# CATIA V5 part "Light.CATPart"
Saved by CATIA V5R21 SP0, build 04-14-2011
Part number: Light
Bounding box of the stored display mesh (mm): x -34.99 to 34.99, y -34.99 to 35, z -65 to 0
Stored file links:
  G:\CATIA\Class\Class_3D\Light.CATPart
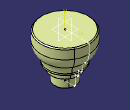
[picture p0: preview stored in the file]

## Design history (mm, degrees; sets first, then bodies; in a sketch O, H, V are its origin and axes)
Set1 "surface"
  Revol1: Element1 Sketch1, Angle1 360
Set2 "Operation"
  Sketch1 on yz-plane, origin (0, 0, 0), H (0, 1, 0), V (0, 0, 1)
    axis line L1 (0, 88.3428) -> (0, -107.8495)
    point P1 (0, 88.3428)
    line L2 (0, 0) -> (33.5858, 0)
    point P3 (35, 0)
    line L3 (35, -1.4142) -> (35, -14)
    point P4 (35, -14)
    arc A1 centre (15, -14) radius 20 from (35, -14) to (29.2857, -27.9971) cw
    arc A2 centre (40, -38.4949) radius 15 from (29.2857, -27.9971) to (25, -38.4949) ccw
    line L4 (25, -38.4949) -> (25, -40.5858)
    line L5 (23.5858, -42) -> (20, -42)
    line L6 (20, -42) -> (20, -48.5858)
    line L7 (18.5858, -50) -> (15, -50)
    line L8 (15, -50) -> (15, -63.5858)
    line L9 (13.5858, -65) -> (0, -65)
    point P11 (0, -65)
    line L10 (33.5858, 0) -> (35, -1.4142)
    line L11 (23.5858, -42) -> (25, -40.5858)
    line L12 (18.5858, -50) -> (20, -48.5858)
    line L13 (13.5858, -65) -> (15, -63.5858)
    "Radius" L3 L1 = 35
    "Radius" L8 L1 = 15
    radius A1 = 20
    radius A2 = 15
    distance L2 L5 = 42
    distance L7 L9 = 15
    distance L2 L9 = 65
    "Radius" L4 L1 = 25
    "Radius" L6 L1 = 20
    distance P3 P4 = 14
    angle L2 L10 = 45
    length L10 = 2
    angle L5 L11 = 45
    length L11 = 2
    angle L7 L12 = 45
    length L12 = 2
    angle L9 L13 = 45
    length L13 = 2
    coincidence: P1 V, P11 V, L2 P3, L3 P3
    vertical: L1 V, L3 V, L4 V, L6 V, L8 V
    horizontal: L2 H, L5 H, L7 H, L9 H
    tangency: A1 L3, A2 A1, L4 A2
Body1 (main body)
